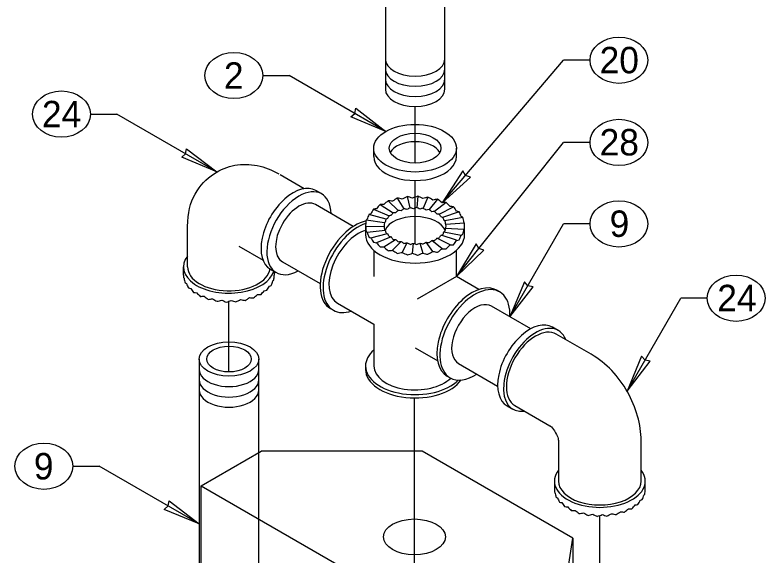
# Model space of a CAD drawing. Extents: x 99862 to 104211, y 98939 to 105076.
# Drawn here: x 100810.9 to 101264.9, y 104258 to 104584.9 of the extents above; entities that cross this region are included whole.
import ezdxf

# ---------------------------------------------------------------- set-up
doc = ezdxf.new("R2010")
doc.units = 0
for name, color, linetype in [('Level 11', 7, 'Continuous'), ('Level 15', 7, 'Continuous'), ('Level 2', 7, 'Continuous'), ('Level 20', 7, 'Continuous'), ('Level 26', 7, 'Continuous'), ('Level 6', 7, 'Continuous'), ('Level 7', 7, 'Continuous'), ('Level 9', 7, 'Continuous')]:
    doc.layers.add(name, color=color, linetype=linetype)

msp = doc.modelspace()

# ---------------------------------------------------------------- linework, layer by layer
at = {"layer": 'Level 11'}
for p, q in [((101028.04, 104499.19), (101028.04, 104504.3)), ((101078.04, 104499.19), (101078.04, 104504.3))]:
    msp.add_line(p, q, dxfattribs=at)
msp.add_ellipse((101053.04, 104504.3), major_axis=(15.62, 0), ratio=0.57735, dxfattribs=at)
for major_axis, start_param, end_param in [((-15.62, 0), 3.428349, 5.996429), ((-25, 0), 6.283185, 9.424778)]:
    msp.add_ellipse((101053.04, 104499.19), major_axis=major_axis, ratio=0.57735, start_param=start_param, end_param=end_param, dxfattribs=at)
at = {"layer": 'Level 15'}
for p, q in [((101069.46, 104471.3), (101142.96, 104557.52)), ((101158.96, 104557.52), (101142.96, 104557.52)), ((100960.83, 104548.3), (100976.83, 104548.3)), ((101035.37, 104514.5), (100976.83, 104548.3)), ((101053.04, 104495.27), (101053.04, 104529.62)), ((100856.47, 104524.96), (100872.47, 104524.96)), ((100933.01, 104490.01), (100872.47, 104524.96)), ((101078.04, 104426.68), (101142.96, 104507.79)), ((101158.96, 104507.79), (101142.96, 104507.79)), ((101053.04, 104446.33), (101053.04, 104484.76)), ((101110.46, 104402.19), (101142.96, 104458.48)), ((101158.96, 104458.48), (101142.96, 104458.48)), ((100940.33, 104368.85), (100940.33, 104411.6)), ((101181.37, 104357.18), (101213.87, 104413.48)), ((101229.87, 104413.48), (101213.87, 104413.48)), ((101052.62, 104231.07), (101052.62, 104353.08)), ((100845.85, 104311.77), (100861.85, 104311.77)), ((100922.39, 104276.82), (100861.85, 104311.77)), ((101164.89, 104239.21), (101164.89, 104281.96))]:
    msp.add_line(p, q, dxfattribs=at)
for points in [[(101035.37, 104514.5), (101014.1, 104523.33), (101016.51, 104525.39), (101017.09, 104528.5)], [(100933.01, 104490.01), (100911.75, 104498.83), (100914.15, 104500.89), (100914.73, 104504.01)], [(101069.46, 104471.3), (101086.54, 104486.74), (101083.58, 104487.87), (101082, 104490.61)], [(101078.04, 104426.68), (101094.64, 104442.64), (101091.65, 104443.68), (101089.98, 104446.37)], [(101110.46, 104402.19), (101124.46, 104420.46), (101121.35, 104421.04), (101119.29, 104423.45)], [(101181.37, 104357.18), (101195.37, 104375.46), (101192.25, 104376.04), (101190.2, 104378.45)], [(100922.39, 104276.82), (100901.12, 104285.65), (100903.53, 104287.71), (100904.11, 104290.82)]]:
    msp.add_lwpolyline(points, close=True, dxfattribs=at)
at = {"layer": 'Level 2'}
msp.add_ellipse((101053.04, 104504.3), major_axis=(25, 0), ratio=0.57735, dxfattribs=at)
at = {"layer": 'Level 20'}
for p, q in [((100971.27, 104488.33), (100985.99, 104479.82)), ((101015.62, 104456.94), (100992.76, 104470.15)), ((100915.33, 104432.41), (100915.33, 104456.91)), ((100972.76, 104435.5), (100995.62, 104422.3)), ((100912.83, 104427.48), (100912.83, 104432.41)), ((100967.83, 104429.69), (100967.83, 104427.48)), ((101123.02, 104394.93), (101099.28, 104408.64)), ((101159.71, 104379.53), (101138.5, 104391.78)), ((101079.28, 104374), (101103.02, 104360.29)), ((101113.5, 104348.47), (101134.71, 104336.23)), ((101139.89, 104327.26), (101139.89, 104302.76)), ((101189.89, 104302.76), (101189.89, 104327.26)), ((101137.39, 104302.76), (101137.39, 104297.83)), ((101192.39, 104297.83), (101192.39, 104302.76))]:
    msp.add_line(p, q, dxfattribs=at)
for centre in [(101176.46, 104557.52), (100943.33, 104548.3), (100838.97, 104524.96), (101176.46, 104507.79), (101176.46, 104458.48), (101247.37, 104413.48), (100828.35, 104311.77)]:
    msp.add_ellipse(centre, major_axis=(-17.5, 0), ratio=0.8, dxfattribs=at)
for centre, major_axis, ratio, start_param, end_param in [((100982.76, 104452.82), (13.75, 23.82), 0.57735, 5.526729, 10.181234), ((100982.76, 104452.82), (-10, -17.32), 0.57735, 3.141593, 6.283185), ((100940.33, 104428.02), (-27.03, -5.37), 0.947565, 6.097095, 6.149455), ((100940.33, 104428.02), (-27.5, -1.68), 0.206802, 0.039705, 0.144424), ((100940.33, 104428.02), (25.29, -11.7), 0.922162, 3.702024, 3.806744), ((100940.33, 104428.02), (-24.52, -14.02), 0.887795, 2.305204, 2.41027), ((100940.33, 104428.02), (27.49, -2.78), 0.21596, 6.043201, 6.148266), ((100940.33, 104428.02), (-27.03, -5.37), 0.947565, 2.798769, 2.903143), ((100940.33, 104428.02), (-27.49, -3.89), 0.223561, 0.230203, 0.334923), ((100940.33, 104428.02), (24.12, -15.48), 0.853385, 4.009326, 4.114045), ((100940.33, 104428.02), (-27.46, -6), 0.252109, 0.416228, 0.520948), ((100940.33, 104428.02), (24.3, -16.43), 0.783391, 4.204501, 4.309221), ((100940.33, 104428.02), (-24.14, -16.11), 0.818147, 2.06586, 2.17058), ((100940.33, 104428.02), (27.48, -4.96), 0.236491, 5.854579, 5.958953), ((100940.33, 104428.02), (-27.4, -7.98), 0.290225, 0.596374, 0.701094), ((100940.33, 104428.02), (24.82, -16.54), 0.715795, 4.372134, 4.476854), ((100940.33, 104428.02), (-25.11, -16.43), 0.682966, 1.726553, 1.831273), ((100940.33, 104428.02), (27.36, -8.91), 0.312139, 5.494389, 5.599109), ((100940.33, 104428.02), (-24.54, -16.55), 0.749264, 1.888318, 1.993037), ((100940.33, 104428.02), (27.43, -7.01), 0.270119, 5.671382, 5.776101), ((100940.33, 104428.02), (-27.3, -9.8), 0.335596, 0.770216, 0.874936), ((100940.33, 104428.02), (25.39, -16.22), 0.650745, 4.530376, 4.635096), ((100940.33, 104428.02), (-27.14, -11.45), 0.386234, 0.938087, 1.042807), ((100940.33, 104428.02), (25.93, -15.58), 0.588004, 4.685558, 4.790278), ((100940.33, 104428.02), (-26.91, -12.9), 0.440657, 1.100807, 1.205527), ((100940.33, 104428.02), (26.39, -14.68), 0.527399, 4.840753, 4.945473), ((100940.33, 104428.02), (-26.58, -14.14), 0.497899, 1.259485, 1.364205), ((100940.33, 104428.02), (26.76, -13.55), 0.468967, 4.997892, 5.102611), ((100940.33, 104428.02), (-26.17, -15.16), 0.557438, 1.415448, 1.520168), ((100940.33, 104428.02), (27.03, -12.2), 0.413044, 5.158439, 5.263158), ((100940.33, 104428.02), (-25.67, -15.94), 0.6191, 1.570348, 1.675068), ((100940.33, 104428.02), (27.23, -10.65), 0.360362, 5.323611, 5.42833), ((101089.28, 104391.32), (10, 17.32), 0.57735, 0, 3.141593), ((101122.46, 104372.17), (13.75, 23.82), 0.57735, 0, 3.141593), ((101164.89, 104298.37), (-27.03, -5.37), 0.947565, 6.097095, 6.149455), ((101164.89, 104298.37), (-27.03, -5.37), 0.947565, 2.798423, 2.903143), ((101164.89, 104298.37), (-27.5, -1.68), 0.206802, 0.039705, 0.144424), ((101164.89, 104298.37), (25.29, -11.7), 0.922162, 3.702024, 3.806744), ((101164.89, 104298.37), (-27.49, -3.89), 0.223561, 0.230203, 0.334923), ((101164.89, 104298.37), (24.12, -15.48), 0.853385, 4.009326, 4.114045), ((101164.89, 104298.37), (-24.4, -14.28), 0.888613, 2.295514, 2.400234), ((101164.89, 104298.37), (27.49, -2.79), 0.213589, 6.04308, 6.1478), ((101164.89, 104298.37), (-27.46, -6), 0.252109, 0.416228, 0.520948), ((101164.89, 104298.37), (24.3, -16.43), 0.783391, 4.204501, 4.309221), ((101164.89, 104298.37), (-24.54, -16.55), 0.749264, 1.888318, 1.993037), ((101164.89, 104298.37), (27.43, -7.01), 0.270119, 5.671382, 5.776101), ((101164.89, 104298.37), (-24.14, -16.11), 0.818147, 2.06586, 2.17058), ((101164.89, 104298.37), (27.48, -4.96), 0.236491, 5.854579, 5.959298), ((101164.89, 104298.37), (-27.4, -7.98), 0.290225, 0.596374, 0.701094), ((101164.89, 104298.37), (24.82, -16.54), 0.715795, 4.372134, 4.476854), ((101164.89, 104298.37), (-27.3, -9.8), 0.335596, 0.770216, 0.874936), ((101164.89, 104298.37), (25.39, -16.22), 0.650745, 4.530376, 4.635096), ((101164.89, 104298.37), (-27.14, -11.45), 0.386234, 0.938087, 1.042807), ((101164.89, 104298.37), (25.93, -15.58), 0.588004, 4.685558, 4.790278), ((101164.89, 104298.37), (-25.67, -15.94), 0.6191, 1.570694, 1.675068), ((101164.89, 104298.37), (27.23, -10.65), 0.360362, 5.323611, 5.42833), ((101164.89, 104298.37), (-25.11, -16.43), 0.682966, 1.726553, 1.831273), ((101164.89, 104298.37), (27.36, -8.91), 0.312139, 5.494389, 5.599109), ((101164.89, 104298.37), (-26.91, -12.9), 0.440657, 1.100807, 1.205527), ((101164.89, 104298.37), (26.39, -14.68), 0.527399, 4.840753, 4.945473), ((101164.89, 104298.37), (-26.58, -14.14), 0.497899, 1.259485, 1.364205), ((101164.89, 104298.37), (26.76, -13.55), 0.468967, 4.997892, 5.102266), ((101164.89, 104298.37), (-26.18, -15.07), 0.558157, 1.416585, 1.52165), ((101164.89, 104298.37), (27.04, -12.13), 0.414287, 5.15799, 5.263055)]:
    msp.add_ellipse(centre, major_axis=major_axis, ratio=ratio, start_param=start_param, end_param=end_param, dxfattribs=at)
for points in [[(100915.33, 104456.91), (100915.34, 104465.13), (100918.68, 104477.7), (100931, 104489.81), (100943.7, 104494.86), (100957.62, 104494.61), (100966.38, 104491.14), (100970.51, 104488.76)], [(101189.89, 104327.26), (101189.88, 104336.96), (101183.84, 104357.93), (101168.89, 104374.22), (101159.71, 104379.53)], [(101134.71, 104336.23), (101134.57, 104336.32), (101136.04, 104335.45), (101138.99, 104330.85), (101139.92, 104327.58), (101139.88, 104327.16), (101139.89, 104327.26)]]:
    msp.add_open_spline(points, degree=3, dxfattribs=at)
at = {"layer": 'Level 26'}
for p, q in [((100923.56, 104299.94), (100959.88, 104320.9)), ((101057.24, 104320.9), (100959.88, 104320.9)), ((101148.63, 104268.14), (101057.24, 104320.9)), ((100923.56, 104204.06), (100923.56, 104299.94)), ((100923.56, 104299.94), (101100.34, 104197.87)), ((101141.29, 104221.52), (101148.63, 104268.14)), ((101148.63, 104268.14), (101148.63, 104251.39))]:
    msp.add_line(p, q, dxfattribs=at)
msp.add_ellipse((101052.62, 104269.01), major_axis=(18.75, 0), ratio=0.57735, dxfattribs=at)
msp.add_ellipse((101052.62, 104269.01), major_axis=(18.75, 0), ratio=0.57735, dxfattribs=at)
at = {"layer": 'Level 6'}
for p, q in [((101042.29, 104474.11), (101046.32, 104467.61)), ((101050.12, 104468.2), (101048.37, 104475.04)), ((101054.61, 104475.24), (101054.02, 104468.32)), ((101060.8, 104474.67), (101057.89, 104467.96)), ((101031.85, 104470.19), (101039.8, 104465.16)), ((101036.72, 104472.47), (101042.84, 104466.59)), ((101066.65, 104473.37), (101061.55, 104467.15)), ((101071.91, 104471.4), (101064.83, 104465.92)), ((101027.91, 104467.38), (101037.33, 104463.41)), ((101067.6, 104464.32), (101076.34, 104468.85)), ((101079.75, 104465.81), (101069.74, 104462.43)), ((101034.54, 104459.21), (101023.44, 104460.66)), ((101035.55, 104461.39), (101025.06, 104464.16)), ((101082, 104462.43), (101071.14, 104460.31)), ((101023.04, 104456.38), (101023.04, 104452.05)), ((101023.07, 104457.37), (101023.07, 104456.38)), ((101023.11, 104457.05), (101034.34, 104456.95)), ((101071.55, 104455.82), (101082.65, 104455.25)), ((101082.98, 104458.86), (101071.75, 104458.08)), ((101083.04, 104452.05), (101083.04, 104457.37)), ((101024.09, 104453.48), (101034.95, 104454.72)), ((101026.34, 104450.1), (101036.35, 104452.6)), ((101078.18, 104448.53), (101068.76, 104451.62)), ((101070.53, 104453.64), (101081.03, 104451.75)), ((101038.48, 104450.71), (101029.75, 104447.06)), ((101034.18, 104444.51), (101041.25, 104449.11)), ((101039.44, 104442.53), (101044.54, 104447.88)), ((101045.29, 104441.24), (101048.2, 104447.07)), ((101051.48, 104440.67), (101052.06, 104446.71)), ((101055.97, 104446.83), (101057.72, 104440.86)), ((101063.8, 104441.8), (101059.76, 104447.42)), ((101069.37, 104443.44), (101063.25, 104448.44)), ((101074.24, 104445.72), (101066.29, 104449.87)), ((101028.04, 104442.47), (101028.04, 104426.68)), ((101078.04, 104426.68), (101078.04, 104442.47)), ((101078.04, 104426.68), (101054.22, 104412.92)), ((101091.72, 104418.78), (101078.04, 104426.68)), ((101104.28, 104417.3), (101102.52, 104418.32)), ((101006.07, 104410.5), (101028.04, 104397.81)), ((101001.8, 104407.19), (101003.57, 104406.16)), ((101028.04, 104397.81), (101028.04, 104372.44)), ((101053.04, 104383.38), (101066.72, 104375.48)), ((101023.04, 104372.44), (101023.04, 104370.4)), ((101072.52, 104366.36), (101074.28, 104365.34))]:
    msp.add_line(p, q, dxfattribs=at)
for centre, major_axis, ratio, start_param, end_param in [((101053.04, 104456.78), (27.98, 17.37), 0.6191, 1.570694, 1.675068), ((101053.04, 104456.78), (-29.47, 13.22), 0.414287, 5.15799, 5.263055), ((101053.04, 104456.78), (28.54, 16.43), 0.558157, 1.416585, 1.52165), ((101053.04, 104456.78), (-29.16, 14.77), 0.468967, 4.997892, 5.102266), ((101053.04, 104456.78), (28.98, 15.42), 0.497899, 1.259485, 1.364205), ((101053.04, 104456.78), (-28.76, 16), 0.527399, 4.840753, 4.945473), ((101053.04, 104456.78), (29.33, 14.06), 0.440657, 1.100807, 1.205527), ((101053.04, 104456.78), (-28.26, 16.99), 0.588004, 4.685558, 4.790278), ((101053.04, 104456.78), (26.75, 18.04), 0.749264, 1.888318, 1.993037), ((101053.04, 104456.78), (-29.82, 9.71), 0.312139, 5.494389, 5.599109), ((101053.04, 104456.78), (27.37, 17.9), 0.682966, 1.726553, 1.831273), ((101053.04, 104456.78), (-29.68, 11.61), 0.360362, 5.323611, 5.42833), ((101053.04, 104456.78), (29.59, 12.48), 0.386234, 0.938087, 1.042807), ((101053.04, 104456.78), (-27.68, 17.68), 0.650745, 4.530376, 4.635096), ((101053.04, 104456.78), (29.76, 10.68), 0.335596, 0.770216, 0.874936), ((101053.04, 104456.78), (-27.05, 18.03), 0.715795, 4.372134, 4.476854), ((101053.04, 104456.78), (26.31, 17.56), 0.818147, 2.06586, 2.17058), ((101053.04, 104456.78), (-29.9, 7.64), 0.270119, 5.671382, 5.776101), ((101053.04, 104456.78), (-16.72, -11.28), 0.749264, 5.02991, 5.13463), ((101053.04, 104456.78), (18.64, -6.07), 0.312139, 2.352796, 2.457516), ((101053.04, 104456.78), (-17.1, -11.19), 0.682966, 4.868145, 4.972865), ((101053.04, 104456.78), (18.55, -7.25), 0.360362, 2.182018, 2.286738), ((101053.04, 104456.78), (-17.49, -10.86), 0.6191, 4.712286, 4.81666), ((101053.04, 104456.78), (18.42, -8.26), 0.414287, 2.016397, 2.121462), ((101053.04, 104456.78), (-17.84, -10.27), 0.558157, 4.558177, 4.663243), ((101053.04, 104456.78), (18.23, -9.23), 0.468967, 1.856299, 1.960673), ((101053.04, 104456.78), (-18.11, -9.64), 0.497899, 4.401077, 4.505797), ((101053.04, 104456.78), (17.98, -10), 0.527399, 1.69916, 1.80388), ((101053.04, 104456.78), (-18.33, -8.79), 0.440657, 4.2424, 4.34712), ((101053.04, 104456.78), (17.66, -10.62), 0.588004, 1.543965, 1.648685), ((101053.04, 104456.78), (-18.49, -7.8), 0.386234, 4.07968, 4.184399), ((101053.04, 104456.78), (17.3, -11.05), 0.650745, 1.388784, 1.493503), ((101053.04, 104456.78), (-18.6, -6.68), 0.335596, 3.911808, 4.016528), ((101053.04, 104456.78), (16.91, -11.27), 0.715795, 1.230542, 1.335261), ((101053.04, 104456.78), (29.87, 8.7), 0.290225, 0.596374, 0.701094), ((101053.04, 104456.78), (-26.49, 17.9), 0.783391, 4.204501, 4.309221), ((101053.04, 104456.78), (29.93, 6.54), 0.252109, 0.416228, 0.520948), ((101053.04, 104456.78), (-26.29, 16.88), 0.853385, 4.009326, 4.114045), ((101016.8, 104433.17), (15, 25.98), 0.57735, 0.470604, 3.141593), ((101053.04, 104456.78), (29.46, 5.85), 0.947565, 2.798423, 2.903143), ((101053.04, 104456.78), (-29.97, 3.04), 0.213589, 6.04308, 6.1478), ((101053.04, 104456.78), (26.59, 15.56), 0.888613, 2.295514, 2.400234), ((101053.04, 104456.78), (-29.95, 5.4), 0.236491, 5.854579, 5.959298), ((101053.04, 104452.05), (-18.75, 0), 0.57735, 3.37462, 6.030205), ((101053.04, 104456.78), (-16.62, -9.73), 0.888613, 5.437107, 5.541827), ((101053.04, 104456.78), (18.72, -3.38), 0.236491, 2.712986, 2.817706), ((101053.04, 104456.78), (-16.44, -10.97), 0.818147, 5.207453, 5.312172), ((101053.04, 104456.78), (18.69, -4.77), 0.270119, 2.529789, 2.634509), ((101053.04, 104456.78), (-18.67, -5.44), 0.290225, 3.737967, 3.842687), ((101053.04, 104456.78), (16.56, -11.19), 0.783391, 1.062908, 1.167628), ((101053.04, 104456.78), (-18.71, -4.09), 0.252109, 3.557821, 3.662541), ((101053.04, 104456.78), (16.43, -10.55), 0.853385, 0.867733, 0.972453), ((101053.04, 104456.78), (-18.73, -2.65), 0.223561, 3.371796, 3.476515), ((101053.04, 104456.78), (17.23, -7.97), 0.922162, 0.560431, 0.665151), ((101053.04, 104456.78), (29.96, 4.24), 0.223561, 0.230203, 0.334923), ((101053.04, 104456.78), (-27.57, 12.76), 0.922162, 3.702024, 3.806744), ((101018.57, 104432.15), (15, 25.98), 0.57735, 0.566145, 3.141593), ((101053.04, 104456.78), (-29.97, 0.61), 0.203365, 6.234982, 6.339702), ((101053.04, 104456.78), (-27.57, 12.76), 0.922162, 0.455712, 0.560431), ((101053.04, 104456.78), (18.73, -0.38), 0.203365, 3.09339, 3.19811), ((101053.04, 104456.78), (-18.41, -3.66), 0.947565, 5.940016, 6.044735), ((101053.04, 104456.78), (17.23, -7.97), 0.922162, 3.597304, 3.702024), ((101053.04, 104456.78), (18.73, -1.9), 0.213589, 2.901488, 3.006207), ((101053.04, 104456.78), (-16.62, -9.73), 0.888613, 2.400234, 2.504954), ((101053.04, 104456.78), (-18.73, -1.15), 0.206802, 3.181297, 3.286017), ((101053.04, 104456.78), (18.73, -0.38), 0.203365, 6.130263, 6.234982), ((101053.04, 104456.78), (-18.41, -3.66), 0.947565, 2.903143, 3.007863), ((101053.04, 104456.78), (29.97, 1.83), 0.206802, 0.039705, 0.144424), ((101053.04, 104456.78), (-29.97, 0.61), 0.203365, 2.98867, 3.09339), ((101053.04, 104456.78), (29.46, 5.85), 0.947565, 6.044735, 6.149455), ((101018.57, 104432.15), (12.5, 21.65), 0.57735, 0.529676, 3.141593), ((101053.04, 104452.05), (30, 0), 0.57735, 3.141593, 6.283185), ((101053.04, 104456.78), (29.97, 1.83), 0.206802, 3.286017, 3.390737), ((101053.04, 104456.78), (-26.29, 16.88), 0.853385, 0.763013, 0.867733), ((101053.04, 104456.78), (-18.73, -1.15), 0.206802, 0.144424, 0.249144), ((101053.04, 104456.78), (16.43, -10.55), 0.853385, 3.904606, 4.009326), ((101053.04, 104456.78), (-18.73, -2.65), 0.223561, 0.334923, 0.439643), ((101053.04, 104456.78), (16.56, -11.19), 0.783391, 4.099781, 4.204501), ((101053.04, 104456.78), (-16.72, -11.28), 0.749264, 1.993037, 2.097757), ((101053.04, 104456.78), (18.72, -3.38), 0.236491, 5.749859, 5.854579), ((101053.04, 104456.78), (-16.44, -10.97), 0.818147, 2.17058, 2.2753), ((101053.04, 104456.78), (18.73, -1.9), 0.213589, 5.93836, 6.04308), ((101053.04, 104456.78), (26.31, 17.56), 0.818147, 5.312172, 5.416892), ((101053.04, 104456.78), (-29.97, 3.04), 0.213589, 2.796768, 2.901488), ((101053.04, 104456.78), (26.59, 15.56), 0.888613, 5.541827, 5.646547), ((101053.04, 104456.78), (29.96, 4.24), 0.223561, 3.476515, 3.581235), ((101053.04, 104456.78), (-26.49, 17.9), 0.783391, 0.958188, 1.062908), ((101053.04, 104456.78), (29.93, 6.54), 0.252109, 3.662541, 3.76726), ((101053.04, 104456.78), (-27.05, 18.03), 0.715795, 1.125822, 1.230542), ((101053.04, 104456.78), (-18.71, -4.09), 0.252109, 0.520948, 0.625668), ((101053.04, 104456.78), (16.91, -11.27), 0.715795, 4.267414, 4.372134), ((101053.04, 104456.78), (-18.67, -5.44), 0.290225, 0.701094, 0.805814), ((101053.04, 104456.78), (17.3, -11.05), 0.650745, 4.425657, 4.530376), ((101053.04, 104456.78), (-18.6, -6.68), 0.335596, 0.874936, 0.979655), ((101053.04, 104456.78), (17.66, -10.62), 0.588004, 4.580838, 4.685558), ((101053.04, 104456.78), (-18.49, -7.8), 0.386234, 1.042807, 1.147526), ((101053.04, 104456.78), (17.98, -10), 0.527399, 4.736033, 4.840753), ((101053.04, 104456.78), (-18.33, -8.79), 0.440657, 1.205527, 1.310247), ((101053.04, 104456.78), (18.23, -9.23), 0.468967, 4.893172, 4.997892), ((101053.04, 104456.78), (-18.11, -9.64), 0.497899, 1.364205, 1.468579), ((101053.04, 104456.78), (18.42, -8.26), 0.414287, 5.052925, 5.15799), ((101053.04, 104456.78), (-17.84, -10.27), 0.558157, 1.52165, 1.626715), ((101053.04, 104456.78), (18.55, -7.25), 0.360362, 5.219236, 5.323611), ((101053.04, 104456.78), (-17.49, -10.86), 0.6191, 1.675068, 1.779788), ((101053.04, 104456.78), (18.64, -6.07), 0.312139, 5.389669, 5.494389), ((101053.04, 104456.78), (-17.1, -11.19), 0.682966, 1.831273, 1.935992), ((101053.04, 104456.78), (18.69, -4.77), 0.270119, 5.566662, 5.671382), ((101053.04, 104456.78), (26.75, 18.04), 0.749264, 5.13463, 5.23935), ((101053.04, 104456.78), (-29.95, 5.4), 0.236491, 2.608266, 2.712986), ((101053.04, 104456.78), (29.87, 8.7), 0.290225, 3.842687, 3.947407), ((101053.04, 104456.78), (-27.68, 17.68), 0.650745, 1.284064, 1.388784), ((101053.04, 104456.78), (29.76, 10.68), 0.335596, 4.016528, 4.121248), ((101053.04, 104456.78), (-28.26, 16.99), 0.588004, 1.439246, 1.543965), ((101053.04, 104456.78), (27.98, 17.37), 0.6191, 4.81666, 4.92138), ((101053.04, 104456.78), (-29.82, 9.71), 0.312139, 2.248076, 2.352796), ((101053.04, 104456.78), (27.37, 17.9), 0.682966, 4.972865, 5.077585), ((101053.04, 104456.78), (-29.9, 7.64), 0.270119, 2.425069, 2.529789), ((101053.04, 104456.78), (29.59, 12.48), 0.386234, 4.184399, 4.289119), ((101053.04, 104456.78), (-28.76, 16), 0.527399, 1.59444, 1.69916), ((101053.04, 104456.78), (29.33, 14.06), 0.440657, 4.34712, 4.45184), ((101053.04, 104456.78), (-29.16, 14.77), 0.468967, 1.751579, 1.856299), ((101053.04, 104456.78), (28.98, 15.42), 0.497899, 4.505797, 4.610172), ((101053.04, 104456.78), (-29.47, 13.22), 0.414287, 1.911332, 2.016397), ((101053.04, 104456.78), (28.54, 16.43), 0.558157, 4.663243, 4.768308), ((101053.04, 104456.78), (-29.68, 11.61), 0.360362, 2.077644, 2.182018), ((101087.52, 104392.34), (15, 25.98), 0.57735, 0, 3.141593), ((101089.28, 104391.32), (15, 25.98), 0.57735, 5.442117, 9.424778), ((101018.57, 104432.15), (15, 25.98), 0.57735, 3.141593, 3.727278), ((101053.04, 104372.44), (30, 0), 0.57735, 2.555907, 3.141593), ((101053.04, 104372.44), (30, 0), 0.57735, 3.141593, 5.770865), ((101053.04, 104370.4), (30, 0), 0.57735, 3.141593, 5.903614), ((101053.04, 104372.44), (25, 0), 0.57735, 3.141593, 5.753951), ((101089.28, 104391.32), (15, 25.98), 0.57735, 3.141593, 3.982661)]:
    msp.add_ellipse(centre, major_axis=major_axis, ratio=ratio, start_param=start_param, end_param=end_param, dxfattribs=at)
at = {"layer": 'Level 7'}
for p, q in [((100996.51, 104476.64), (100992.97, 104478.68)), ((100946.27, 104445.02), (100960.99, 104436.52)), ((100965.47, 104431.05), (100969.01, 104429.01)), ((101139.75, 104393.94), (101136.21, 104395.98)), ((101108.71, 104348.35), (101112.25, 104346.31))]:
    msp.add_line(p, q, dxfattribs=at)
for centre, major_axis, ratio, start_param, end_param in [((100979.22, 104454.87), (13.75, 23.82), 0.57735, 0, 3.141593), ((100940.33, 104432.41), (27.5, 0), 0.57735, 2.711893, 6.123637), ((100940.33, 104432.41), (25, 0), 0.57735, 3.141593, 6.198272), ((100940.33, 104428.02), (27.5, -0.56), 0.203365, 6.234982, 6.287342), ((101126, 104370.12), (13.75, 23.82), 0.57735, 5.853486, 9.854478), ((101126, 104370.12), (-12.5, -21.65), 0.57735, 3.141593, 6.283185), ((101164.89, 104302.76), (-27.5, 0), 0.57735, 5.853486, 9.854478), ((101164.89, 104302.76), (-25, 0), 0.57735, 0, 3.141593), ((101164.89, 104298.37), (27.5, -0.56), 0.203365, 6.234982, 6.287342)]:
    msp.add_ellipse(centre, major_axis=major_axis, ratio=ratio, start_param=start_param, end_param=end_param, dxfattribs=at)
at = {"layer": 'Level 9'}
for p, q in [((101035.04, 104671.79), (101035.04, 104540.01)), ((101071.04, 104540.01), (101071.04, 104671.79)), ((100922.39, 104376.65), (100922.39, 104176.62)), ((100958.39, 104176.62), (100958.39, 104376.65))]:
    msp.add_line(p, q, dxfattribs=at)
for centre, start_param in [((101053.04, 104558.29), 3.141593), ((101053.04, 104552.16), 3.141593), ((101053.04, 104546.03), 3.141593), ((101053.04, 104540.01), 3.141593), ((100940.39, 104370.36), 3.141588), ((100940.39, 104364.05), 3.141587), ((100940.39, 104357.92), 3.141585)]:
    msp.add_ellipse(centre, major_axis=(18, 0), ratio=0.57735, start_param=start_param, end_param=6.283185, dxfattribs=at)
for major_axis in [(18, 0), (13.5, 0)]:
    msp.add_ellipse((100940.39, 104376.65), major_axis=major_axis, ratio=0.57735, dxfattribs=at)

# ---------------------------------------------------------------- texts
at = {"layer": 'Level 20'}
for s, p in [('20', (101164.76, 104549.65)), ('2', (100937.34, 104540.3)), ('24', (100827.14, 104516.96)), ('28', (101164.76, 104499.92)), ('9', (101170.81, 104450.61)), ('24', (101235.97, 104405.61)), ('9', (100822.26, 104303.77))]:
    msp.add_text(s, height=16, dxfattribs=at).set_placement(p)

doc.saveas('drawing.dxf')
